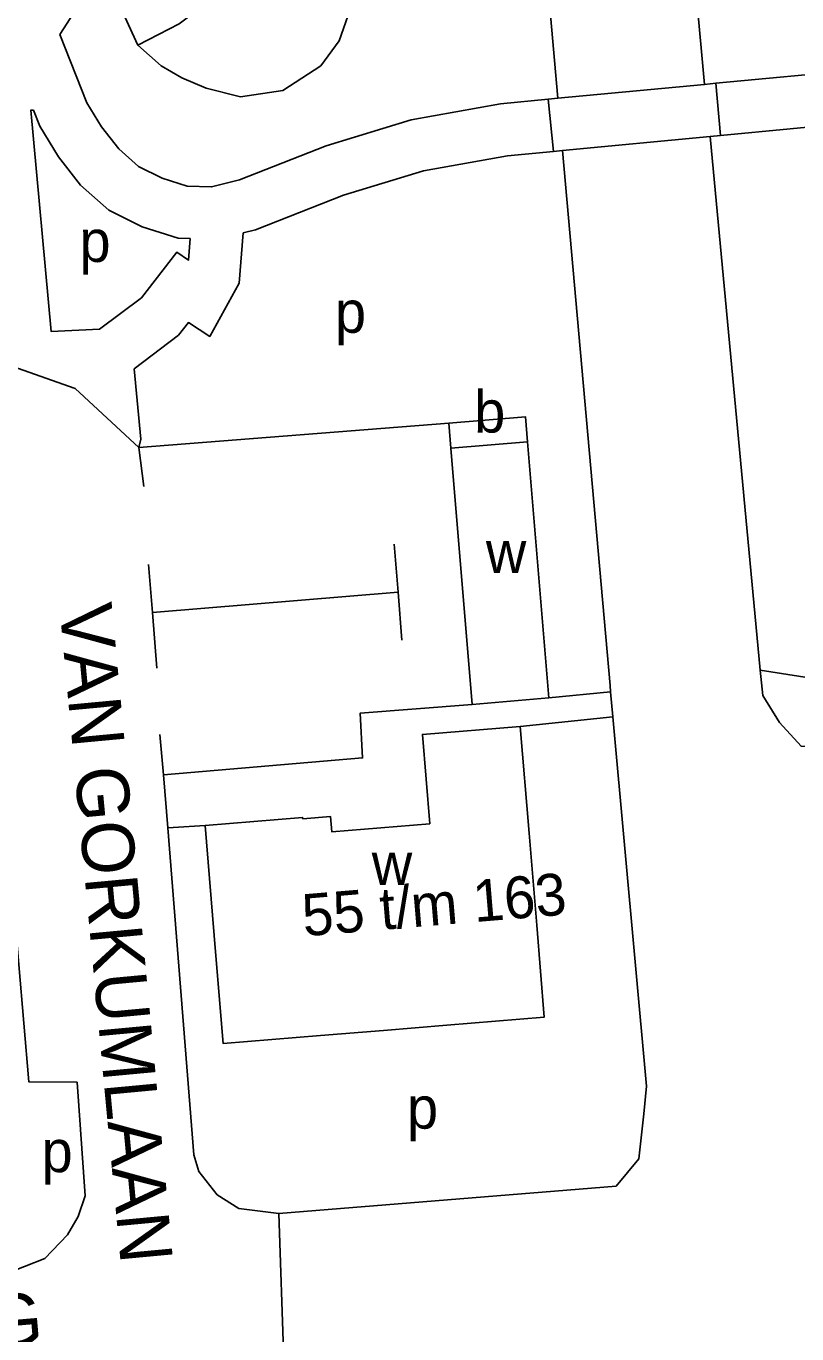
# Model space of a CAD drawing. Extents: x 163026 to 166241, y 382475 to 384501.
# Drawn here: x 164257.7 to 164331.2, y 383848 to 383972.8 of the extents above; entities that cross this region are included whole.
import ezdxf

# ---------------------------------------------------------------- set-up
doc = ezdxf.new("R2010")
doc.units = 0
for name, color, linetype in [('BLT_Basislijn', 7, 'Continuous'), ('BLT_Bebouwing', 7, 'Continuous'), ('BLT_Centroide', 7, 'Continuous'), ('BLT_Huisnummer_reeks', 7, 'Continuous'), ('BLT_Onderverdeling_panden', 7, 'Continuous'), ('BLT_Straatnaam', 7, 'Continuous'), ('BLT_Vlakafsluiter', 7, 'Continuous')]:
    doc.layers.add(name, color=color, linetype=linetype)

msp = doc.modelspace()

# ---------------------------------------------------------------- linework, layer by layer
at = {"layer": 'BLT_Basislijn'}
for p, q in [((164318.32, 384012.79), (164322.4, 383967.25)), ((164263.4, 383975.92), (164260.88, 383972.01)), ((164266.71, 383974.47), (164268.32, 383970.99)), ((164322.4, 383967.25), (164308.41, 383965.92)), ((164323.49, 383967.35), (164322.4, 383967.25)), ((164323.49, 383967.35), (164323.93, 383962.37)), ((164307.49, 383965.83), (164302.94, 383965.39)), ((164308.41, 383965.92), (164307.49, 383965.83)), ((164307.99, 383960.85), (164307.49, 383965.83)), ((164322.95, 383962.28), (164308.85, 383960.94)), ((164323.93, 383962.37), (164322.95, 383962.28)), ((164327.71, 383911.37), (164322.95, 383962.28)), ((164307.99, 383960.85), (164303.61, 383960.44)), ((164308.85, 383960.94), (164307.99, 383960.85)), ((164268.4, 383932.62), (164297.99, 383934.94)), ((164292.79, 383923.37), (164293.16, 383918.8)), ((164269.34, 383921.44), (164269.71, 383916.87)), ((164269.71, 383916.87), (164293.16, 383918.8)), ((164293.16, 383918.8), (164293.52, 383914.22)), ((164269.71, 383916.87), (164270.14, 383911.56)), ((164307.53, 383908.71), (164313.44, 383909.28)), ((164313.44, 383909.28), (164313.64, 383906.9)), ((164304.81, 383906), (164313.64, 383906.9)), ((164270.4, 383905.22), (164270.77, 383901.37)), ((164271.17, 383896.33), (164270.77, 383901.37)), ((164274.74, 383896.54), (164271.17, 383896.33))]:
    msp.add_line(p, q, dxfattribs=at)
for points in [[(164308.41, 383965.92), (164303.39, 384022.47), (164299.8, 384050.05)], [(164285.11, 383996.33), (164284.76, 383991.91), (164283.64, 383987.46), (164281.76, 383983.16), (164279.15, 383979.22), (164275.92, 383975.8), (164272.26, 383973.04), (164268.32, 383970.99)], [(164268.32, 383970.99), (164270.53, 383969.01), (164272.52, 383967.87), (164274.84, 383966.89), (164278.11, 383966.07), (164282.16, 383966.67), (164285.78, 383969.02), (164287.52, 383971.42), (164288.59, 383974.38), (164288.66, 383977.2), (164291.44, 383987.56), (164289.58, 383990.68), (164285.11, 383996.33)], [(164260.88, 383972.01), (164263.46, 383965.48), (164264.85, 383963.19), (164266.51, 383961.09), (164268.37, 383959.43), (164270.62, 383958.31), (164273.01, 383957.55), (164275.36, 383957.47), (164278.01, 383958.15)], [(164341.08, 383968.42), (164337.14, 383968.65), (164323.49, 383967.35)], [(164258.36, 383964.78), (164258.09, 383964.78), (164260.05, 383943.67), (164264.66, 383943.89)], [(164258.36, 383964.78), (164258.96, 383963.25), (164260.73, 383960.33), (164262.85, 383957.65), (164265.54, 383955.25), (164268.74, 383953.66), (164272.16, 383952.58), (164273.32, 383952.54)], [(164302.94, 383965.39), (164294.41, 383963.88), (164286.29, 383961.4), (164278.01, 383958.15)], [(164340.07, 383963.47), (164337.23, 383963.64), (164323.93, 383962.37)], [(164340.07, 383963.47), (164343.28, 383959.52), (164344.81, 383954.9), (164349.71, 383948.91), (164350.93, 383945.5), (164350.93, 383941.2), (164349.12, 383936.5), (164336.88, 383918.62), (164334.83, 383912.29), (164334.18, 383911.61), (164332.38, 383910.64), (164327.71, 383911.37)], [(164308.85, 383960.94), (164313.38, 383909.91), (164313.44, 383909.28)], [(164303.61, 383960.44), (164295.58, 383959.01), (164287.94, 383956.68), (164279.54, 383953.38), (164278.38, 383953.08)], [(164273.32, 383952.54), (164273.16, 383950.49), (164272.02, 383951.24), (164268.65, 383946.9), (164264.66, 383943.89)], [(164278.38, 383953.08), (164278, 383948.29), (164275.17, 383943.2), (164273.14, 383944.53), (164272.19, 383943.31), (164267.96, 383940.12)], [(164255.75, 383940.57), (164262.33, 383938.23), (164268.4, 383932.62)], [(164268.4, 383932.62), (164268.59, 383933.4), (164267.96, 383940.12)], [(164268.9, 383928.88), (164268.4, 383932.62)], [(164251.4, 383853.34), (164255.54, 383853.71), (164259.43, 383855.23), (164261.59, 383857.49), (164262.61, 383859.23), (164263.28, 383861.2), (164262.52, 383872.04), (164257.9, 383872.09), (164254.07, 383916.87), (164253.02, 383926.4), (164251.37, 383928.04), (164248.48, 383927.94), (164245.42, 383927.67)], [(164327.71, 383911.37), (164327.98, 383908.95), (164329.55, 383906.38), (164331.62, 383904.1), (164337.59, 383903.81)], [(164270.77, 383901.37), (164289.77, 383902.99), (164289.54, 383907.27), (164300.22, 383908.1)], [(164281.77, 383859.53), (164313.96, 383862.13), (164316.14, 383864.74), (164316.62, 383869.03), (164316.86, 383871.68), (164313.67, 383906.55), (164313.64, 383906.9)], [(164271.17, 383896.33), (164273.65, 383865.13), (164274.12, 383863.53), (164275.87, 383861.32), (164277.94, 383859.99), (164281.77, 383859.53)]]:
    msp.add_lwpolyline(points, dxfattribs=at)
at = {"layer": 'BLT_Bebouwing'}
for p, q in [((164297.99, 383934.94), (164298.19, 383932.55)), ((164298.19, 383932.55), (164300.22, 383908.1)), ((164307.53, 383908.71), (164305.5, 383933.15)), ((164300.22, 383908.1), (164307.53, 383908.71)), ((164304.81, 383906), (164305.66, 383895.82)), ((164275.74, 383884.5), (164274.74, 383896.54)), ((164305.66, 383895.82), (164306.39, 383887.04)), ((164297.79, 383877.5), (164291.77, 383877)), ((164291.77, 383877), (164285.76, 383876.5))]:
    msp.add_line(p, q, dxfattribs=at)
for points in [[(164305.5, 383933.15), (164305.3, 383935.54), (164297.99, 383934.94)], [(164296.19, 383896.71), (164295.48, 383905.23), (164304.81, 383906)], [(164274.74, 383896.54), (164284.04, 383897.31), (164284.05, 383897.18), (164286.7, 383897.41), (164286.82, 383895.94), (164296.19, 383896.71)], [(164306.39, 383887.04), (164307.11, 383878.27), (164297.79, 383877.5)], [(164285.76, 383876.5), (164276.47, 383875.73), (164275.74, 383884.5)]]:
    msp.add_lwpolyline(points, dxfattribs=at)
at = {"layer": 'BLT_Onderverdeling_panden'}
msp.add_line((164298.19, 383932.55), (164305.5, 383933.15), dxfattribs=at)
at = {"layer": 'BLT_Vlakafsluiter'}
msp.add_line((164282.24, 383845.47), (164281.77, 383859.53), dxfattribs=at)

# ---------------------------------------------------------------- texts
at = {"layer": 'BLT_Centroide'}
for s, p in [('p', (164262.74, 383950.31)), ('p', (164287.12, 383943.55)), ('b', (164300.41, 383934.03)), ('w', (164301.53, 383920.62)), ('w', (164290.64, 383890.88)), ('p', (164294, 383867.62)), ('p', (164259.12, 383863.47))]:
    msp.add_text(s, height=4, dxfattribs=at).set_placement(p)
at = {"layer": 'BLT_Huisnummer_reeks'}
msp.add_text('55 t/m 163', height=4, rotation=4.7443, dxfattribs=at).set_placement((164284.16, 383885.97))
at = {"layer": 'BLT_Straatnaam'}
for s, rotation, p in [('VAN GORKUMLAAN', 275.3355, (164260.82, 383917.5)), ('KAARTMAKERSRING', 4.8284, (164192.39, 383841.45))]:
    msp.add_text(s, height=5, rotation=rotation, dxfattribs=at).set_placement(p)

doc.saveas('drawing.dxf')
